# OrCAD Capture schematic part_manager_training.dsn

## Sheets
1 PAGE1: size A; title: EMA DESIGN AUTOMATION; rev: B; note: CIP DEMO
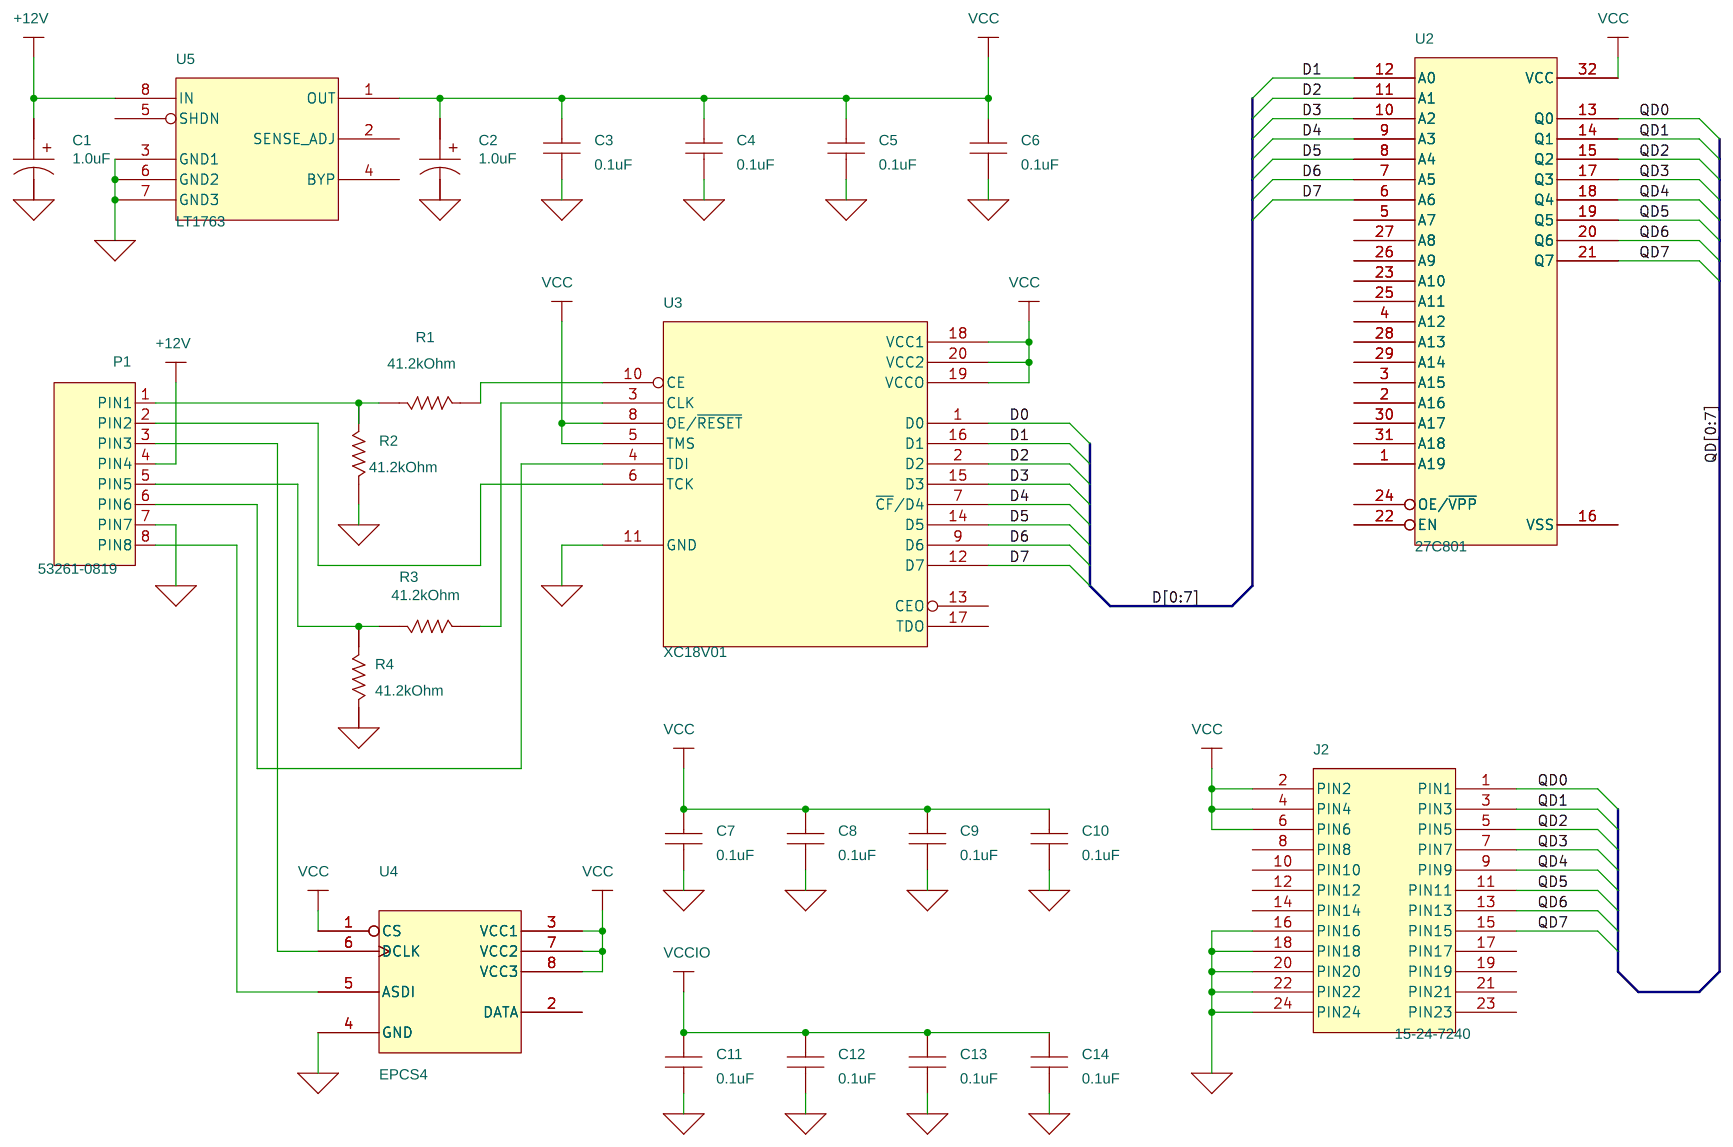
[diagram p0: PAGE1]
2 PAGE2: title: LESSON8

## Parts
C1  1.0uF  [CAPMP3216X180N]
C2  1.0uF  [CAPMP3216X180N]
C3  0.1uF  [CAPC1608X86N]
C4  0.1uF  [CAPC1608X86N]
C5  0.1uF  [CAPC1608X86N]
C6  0.1uF  [CAPC1608X86N]
C7  0.1uF  [CAPC2012X71N]
C8  0.1uF  [CAPC2012X71N]
C9  0.1uF  [CAPC2012X71N]
C10  0.1uF  [CAPC2012X71N]
C11  0.1uF  [CAPC2012X71N]
C12  0.1uF  [CAPC2012X71N]
C13  0.1uF  [CAPC2012X71N]
C14  0.1uF  [CAPC2012X71N]
J2  15-24-7240  [MOLEX_42385-24]
P1  53261-0819  [MOLEX_53261-8_FITNAIL]
R1  41.2kOhm  [RESC1608X55N]
R2  41.2kOhm  [RESC1608X55N]
R3  41.2kOhm  [RESC1608X55N]
R4  41.2kOhm  [RESC1608X55N]
U2  27C801  [DIP32-600]
U3  XC18V01  [SOIC127P1034X267-20N]
U4  EPCS4  [SOIC127P600X175-8N]
U5  LT1763  [SOIC127P600X175-8N]

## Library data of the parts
C1 C2 = CAP_P: CAP, Tantalum, SMD, 1.0 uF, 20 %, 20 V, 3216-18; CLASS: DISCRETE; Dielectric Type: Tantalum; Manufacturer: AVX; Manufacturer PN: TAJA105M020R; PART_NUMBER: EMA-00000454; PSpiceTemplate: C^@REFDES %1 %2 C^@REFDES 1.0uF \n.model C^@REFDES CAP C=1 DEV=0.2; Package Size: 3216-18; Rated Voltage: 20 V; Tolerance: 20%
C3 = CAP: CAP, Ceramic, SMD, 0.1 uF, 10 %, 16 V, 0603; CLASS: DISCRETE; Dielectric Type: Ceramic; Manufacturer: AVX; Manufacturer PN: 0603YC104KA72A; PART_NUMBER: EMA-00000399V22; Package Size: 0603; Rated Voltage: 16 V; Temperature Coefficient: X7R; Tolerance: 10%
C4-C6 = CAP: CAP, Ceramic, SMD, 0.1 uF, 10 %, 16 V, 0603; CLASS: DISCRETE; Dielectric Type: Ceramic; Manufacturer: AVX; Manufacturer PN: 0603YC104KA72A; PART_NUMBER: EMA-00000399V22; PSpiceTemplate: C^@REFDES %1 %2 C^@REFDES 0.1uF \n.model C^@REFDES CAP C=1 DEV=0.1; Package Size: 0603; Rated Voltage: 16 V; Temperature Coefficient: X7R; Tolerance: 10%
C7-C10 = CAP: CAP, Ceramic, SMD, 0.1 uF, 5.0 %, 50 V, 0805; CLASS: DISCRETE; Dielectric Type: Ceramic; Manufacturer: AVX; Manufacturer PN: 08055C104JA72A; PART_NUMBER: EMA-00000407V22; PSpiceTemplate: C^@REFDES %1 %2 C^@REFDES 0.1uF \n.model C^@REFDES CAP C=1 DEV=0.05; Package Size: 0805; Rated Voltage: 50 V; Temperature Coefficient: X7R; Tolerance: 5.0%
C11-C14 = CAP: CAP, Ceramic, SMD, 0.1 uF, 10 %, 25 V, 0805; CLASS: DISCRETE; Dielectric Type: Ceramic; Manufacturer: AVX; Manufacturer PN: 08053C104KAT2A; PART_NUMBER: EMA-00000403; Package Size: 0805; Rated Voltage: 25 V; Temperature Coefficient: X7R; Tolerance: 10%
J2 = HDR_2X12_F: CONN, Header, 15-24-7240, 24, TH; CLASS: IO; Contact Voltage: 600 V; Manufacturer: Molex Inc; Operating Temperature Maximum: 105 C; Operating Temperature Minimum: -40 C; PART_NUMBER: EMA-00005995; Package Size: 51.6 x 9.6 x 11.34 mm
P1 = HDR_1X8_M: CONN, Header, 53261-0819, 8, SMD; CLASS: IO; Manufacturer: Molex Inc; PART_NUMBER: EMA-00006083V22; Package Size: 14.75 x 4.2 x 3.4 mm
R1-R4 = RES: RES, Thin Film, 41.2 kOhm, 0.1 %, 1/16 W, SMD, 0603; CLASS: DISCRETE; Manufacturer: Koa Speer; Manufacturer PN: RN731JTTD4122B25; PART_NUMBER: EMA-00002890V22; PSpiceTemplate: R^@REFDES %1 %2 R^@REFDES =41.2k  \n.model R^@REFDES RES R=1 DEV=0.001 TC1=25u; Package Size: 0603; Rated Power: 1/16 W; Temperature Coefficient: +/-25 ppm; Tolerance: 0.1%
U2 = M27_CW_801_FBK: IC, Memory Devices, EEPROM, 27C801, DIP-32; CLASS: IC; Manufacturer: STMicroelectronics; Manufacturer PN: M27C801-100F1; Operating Temperature Maximum: 70 C; Operating Temperature Minimum: 0.0 C; PART_NUMBER: EMA-00007179; Package Size: DIP-32; Supply Voltage: 5.0 V
U3 = XC18VXXXSO20: IC, Memory Devices, PROM, XC18V01, SOIC-20; CLASS: IC; Manufacturer: Xilinx; Manufacturer PN: XC18V01SOG20C; Operating Temperature Maximum: 85 C; Operating Temperature Minimum: -40 C; PART_NUMBER: EMA-00007402; Package Size: SOIC-20; Supply Voltage: 3.6 V
U4 = EPCSXXXX_8P: IC, Programmable Devices, Config Device, EPCS4, SOIC-8; CLASS: IC; Manufacturer: Altera Corporation; Manufacturer PN: EPCS4SI8N; Operating Temperature Maximum: 150 C; Operating Temperature Minimum: -65 C; PART_NUMBER: EMA-00006523; Package Size: SOIC-8; Rated Power: 54 mW; Supply Voltage: 3.3 V
U5 = REG_1X_8P_LT1763: IC, Voltage Regulator, Linear-LDO, LT1763, SOIC-8; CLASS: IC; Manufacturer: Linear Technology; Manufacturer PN: LT1763CS8-3#PBF; PART_NUMBER: EMA-00006788V22; Package Size: SOIC-8; Supply Voltage: 1.8 - 20 V

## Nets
+12V: C1.1 P1.4(PIN4) U5.8(IN)
GND_SIGNAL: C1.2 C2.2 C3.2 C4.2 C5.2 C6.2 C7.2 C8.2 C9.2 C10.2 C11.2 C12.2 C13.2 C14.2 J2.16(PIN16) J2.18(PIN18) J2.20(PIN20) J2.22(PIN22) J2.24(PIN24) P1.7(PIN7) R2.1 R4.1 U3.11(GND) U4.4(GND) U5.3(GND1) U5.6(GND2) U5.7(GND3)
VCC: C2.1 C3.1 C4.1 C5.1 C6.1 C7.1 C8.1 C9.1 C10.1 J2.2(PIN2) J2.4(PIN4) J2.6(PIN6) U2.32(VCC) U3.5(TMS) U3.8(OE/~{RESET}) U3.18(VCC1) U3.19(VCCO) U3.20(VCC2) U4.1(CS) U4.3(VCC1) U4.7(VCC2) U4.8(VCC3) U5.1(OUT)
VCCIO: C11.1 C12.1 C13.1 C14.1
VSS: U2.16(VSS)
D0: U3.1(D0)
D1: U2.12(A0) U3.16(D1)
D2: U2.11(A1) U3.2(D2)
D3: U2.10(A2) U3.15(D3)
D4: U2.9(A3) U3.7(~{CF}/D4)
D5: U2.8(A4) U3.14(D5)
D6: U2.7(A5) U3.9(D6)
D7: U2.6(A6) U3.12(D7)
QD0: J2.1(PIN1) U2.13(Q0)
QD1: J2.3(PIN3) U2.14(Q1)
QD2: J2.5(PIN5) U2.15(Q2)
QD3: J2.7(PIN7) U2.17(Q3)
QD4: J2.9(PIN9) U2.18(Q4)
QD5: J2.11(PIN11) U2.19(Q5)
QD6: J2.13(PIN13) U2.20(Q6)
QD7: J2.15(PIN15) U2.21(Q7)
N00520: P1.5(PIN5) R3.1 R4.2
N00614: P1.1(PIN1) R1.1 R2.2
N02570: R1.2 U3.10(CE)
N02663: R3.2 U3.3(CLK)
N02853: P1.2(PIN2) U3.6(TCK)
N06329: P1.3(PIN3) U4.6(DCLK)
N11467: P1.6(PIN6) U3.4(TDI)
N139387: P1.8(PIN8) U4.5(ASDI)

Not connected (* = marked no-connect by the designer): J2 8(PIN8) 10(PIN10) 12(PIN12) 14(PIN14) 17(PIN17) 19(PIN19) 21(PIN21) 23(PIN23); U2 1(A19) 2(A16) 3(A15) 4(A12) 5(A7) 22(EN) 23(A10) 24(OE/~{VPP}) 25(A11) 26(A9) 27(A8) 28(A13) 29(A14) 30(A17) 31(A18); U3 13(CEO) 17(TDO); U4 2(DATA); U5 2(SENSE_ADJ) 4(BYP) 5(SHDN)
